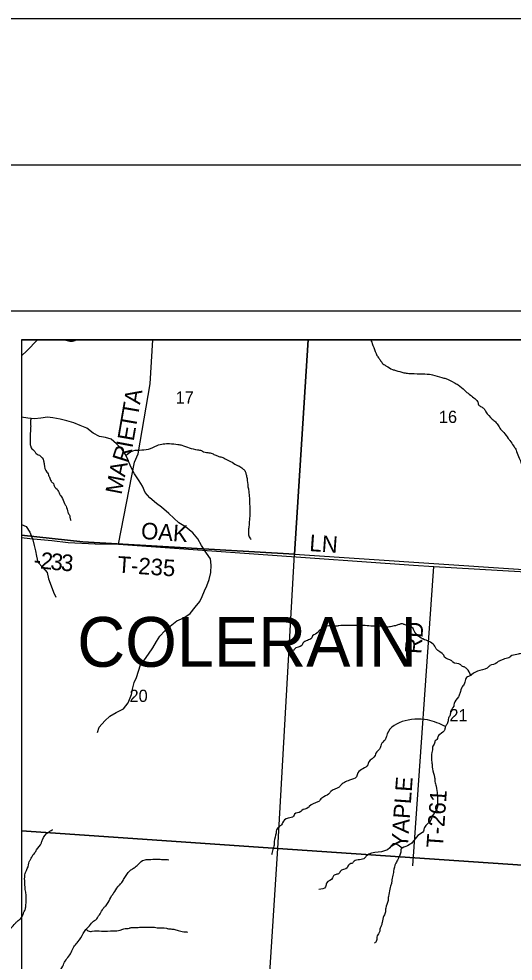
# Model space of a CAD drawing. Extents: x -13.1 to 43.1, y 0 to 22.
# Drawn here: x 2.09 to 3.786, y 18.772 to 22 of the extents above; entities that cross this region are included whole.
import ezdxf

# ---------------------------------------------------------------- set-up
doc = ezdxf.new("R2010")
doc.units = 0
for name, color, linetype in [('Default', 7, 'Continuous'), ('GM_X_Corporation', 7, 'Continuous'), ('GM_X_County_Road', 7, 'Continuous'), ('GM_X_County_Road_Text', 7, 'Continuous'), ('GM_X_Minor_River', 7, 'Continuous'), ('GM_X_Section_Text', 7, 'Continuous'), ('GM_X_State_Route', 7, 'Continuous'), ('GM_X_Township_Road', 7, 'Continuous'), ('GM_X_Township_Road_Text', 7, 'Continuous'), ('GM_X_Township_Text', 7, 'Continuous'), ('SH_Border', 7, 'Continuous'), ('SH_Data', 7, 'Continuous')]:
    doc.layers.add(name, color=color, linetype=linetype)

msp = doc.modelspace()

# ---------------------------------------------------------------- linework, layer by layer
at = {"layer": 'Default'}
msp.add_line((2.3057, 20.9), (2.2471, 20.9), dxfattribs=at)
for centre, major_axis, start_param, end_param in [((2.269, 20.9361), (0.0501, 0), 4.26168, 4.996735), ((2.2979, 20.8669), (0.0412, 0), 1.495662, 1.94098), ((2.3016, 20.9211), (0.0267, 0), 4.691044, 4.868584)]:
    msp.add_ellipse(centre, major_axis=major_axis, ratio=0.8, start_param=start_param, end_param=end_param, dxfattribs=at)
at = {"layer": 'GM_X_Corporation'}
for points in [[(7.0807, 20.9), (2.1, 20.9), (2.1, 14.1), (6.6193, 14.1), (6.6994, 15.2069), (6.7531, 15.956), (6.8236, 16.9075), (6.9509, 19.0179), (7.0108, 19.8446), (7.0164, 19.8954), (7.0617, 20.6133)], [(3.083, 20.9), (2.1, 20.9), (2.1, 20.2313), (2.31, 20.2083), (3.0353, 20.1657)], [(7.0804, 20.9), (2.1, 20.9), (2.1, 14.1), (6.619, 14.1), (6.6992, 15.2074), (6.7528, 15.9566), (6.8234, 16.908), (6.8365, 17.1257), (6.9507, 19.0184), (6.9616, 19.1692), (7.0106, 19.8452), (7.0162, 19.896), (7.0615, 20.6138)], [(7.0804, 20.9), (2.1, 20.9), (2.1, 17.2152), (2.1437, 17.2135), (2.8442, 17.1637), (3.8328, 17.0966), (4.4304, 17.0575), (6.8234, 16.908), (6.8365, 17.1257), (6.9507, 19.0184), (6.9616, 19.1692), (7.0106, 19.8452), (7.0162, 19.896), (7.0615, 20.6138)], [(4.0793, 20.9), (3.083, 20.9), (3.0353, 20.1657), (4.0252, 20.1002)], [(2.1, 20.2313), (2.1, 19.2176), (2.978, 19.1575), (3.0353, 20.1657), (2.31, 20.2083)], [(3.0353, 20.1657), (4.0252, 20.1002), (3.9684, 19.0905), (2.978, 19.1575)], [(2.1, 19.2176), (2.1, 18.2234), (2.9147, 18.1656), (2.978, 19.1575)], [(2.978, 19.1575), (3.9684, 19.0905), (3.9134, 18.1046), (2.9147, 18.1656)]]:
    msp.add_lwpolyline(points, close=True, dxfattribs=at)
at = {"layer": 'GM_X_County_Road'}
msp.add_lwpolyline([(2.1, 20.223), (2.1285, 20.22), (2.2036, 20.2129), (2.26, 20.206), (2.3521, 20.2017), (2.4322, 20.2003), (2.4865, 20.4809), (2.4991, 20.5096), (2.5404, 20.7501), (2.5504, 20.9)], dxfattribs=at)
at = {"layer": 'GM_X_Minor_River'}
for points in [[(2.36, 19.5553), (2.3662, 19.5727), (2.3853, 19.5953), (2.4029, 19.6111), (2.4242, 19.6238), (2.4492, 19.6358), (2.4653, 19.6561), (2.4769, 19.6849), (2.4801, 19.703), (2.4863, 19.7258), (2.494, 19.7439), (2.501, 19.7651), (2.5072, 19.7863), (2.521, 19.8044), (2.5356, 19.8232), (2.5501, 19.8451), (2.5624, 19.867), (2.5739, 19.8851), (2.5915, 19.9032), (2.6098, 19.919), (2.6326, 19.937), (2.6562, 19.9482), (2.6775, 19.9632), (2.6951, 19.9843), (2.7111, 20.0039), (2.7189, 20.0213), (2.7273, 20.0402), (2.7351, 20.0576), (2.7436, 20.0795), (2.7491, 20.1037), (2.75, 20.128), (2.7472, 20.15), (2.7337, 20.1691), (2.7165, 20.1958), (2.7046, 20.2187), (2.6866, 20.2393), (2.6617, 20.26), (2.6391, 20.2731), (2.6053, 20.3052), (2.5798, 20.3274), (2.5624, 20.3397), (2.5391, 20.3589), (2.5241, 20.3772), (2.5145, 20.3993), (2.5033, 20.4168), (2.4868, 20.4412), (2.4749, 20.4656), (2.4645, 20.49), (2.4563, 20.5075), (2.4451, 20.525), (2.4256, 20.5442), (2.4075, 20.5595), (2.3879, 20.5657), (2.3675, 20.5689), (2.3456, 20.5805), (2.323, 20.5981), (2.3004, 20.6067), (2.2785, 20.6159), (2.2551, 20.623), (2.2317, 20.6285), (2.2075, 20.6332), (2.1886, 20.6349), (2.1658, 20.632), (2.1446, 20.6299), (2.1212, 20.6317), (2.1, 20.6349)], [(2.1, 20.2674), (2.1151, 20.2607), (2.1286, 20.2408), (2.1382, 20.215), (2.1434, 20.1952), (2.147, 20.177), (2.1514, 20.1587), (2.155, 20.139), (2.1723, 20.1206), (2.1873, 20.103), (2.1924, 20.081), (2.2013, 20.0574), (2.2095, 20.0353), (2.2169, 20.0186)]]:
    msp.add_lwpolyline(points, dxfattribs=at)
for points in [[(3.2976, 20.9), (3.3036, 20.8839), (3.3081, 20.874), (3.3184, 20.8467), (3.3255, 20.8367), (3.3329, 20.8258), (3.3369, 20.8207), (3.3416, 20.8161), (3.3464, 20.813), (3.3514, 20.8103), (3.3713, 20.799), (3.383, 20.7955), (3.4109, 20.7875), (3.4275, 20.7854), (3.4656, 20.7841), (3.4988, 20.7821), (3.509, 20.7804), (3.5407, 20.7713), (3.555, 20.7673), (3.5839, 20.7533), (3.5967, 20.7463), (3.6196, 20.7267), (3.6504, 20.7021), (3.6635, 20.689), (3.6649, 20.6864), (3.6655, 20.6834), (3.666, 20.6803), (3.6672, 20.6776), (3.6715, 20.6738), (3.6767, 20.6707), (3.6818, 20.6677), (3.686, 20.6637), (3.692, 20.6538), (3.7141, 20.6289), (3.725, 20.6189), (3.7303, 20.6124), (3.735, 20.6053), (3.7396, 20.5981), (3.7448, 20.5914), (3.7534, 20.583), (3.7684, 20.5627), (3.7747, 20.5551), (3.7863, 20.5368), (3.7945, 20.5257), (3.7971, 20.5177), (3.806, 20.4953), (3.8105, 20.4858), (3.8201, 20.4546), (3.8245, 20.4413), (3.827, 20.4327), (3.8291, 20.4241), (3.8313, 20.4154), (3.8337, 20.4068), (3.8386, 20.3942), (3.8482, 20.3635), (3.8522, 20.3521), (3.8585, 20.3244), (3.8633, 20.3092), (3.8647, 20.2997), (3.8694, 20.2766), (3.872, 20.2694), (3.8761, 20.2515), (3.8798, 20.2432), (3.8809, 20.2375), (3.8857, 20.2238), (3.8891, 20.2185), (3.8984, 20.1994), (3.9007, 20.1962), (3.9033, 20.1932), (3.9061, 20.1903), (3.9085, 20.1872), (3.9122, 20.1796), (3.9298, 20.1593), (3.9354, 20.1556), (3.9418, 20.153), (3.9482, 20.1506), (3.9539, 20.1472), (3.9572, 20.1422), (3.9659, 20.1383), (3.9817, 20.1302)], [(2.1314, 20.6309), (2.1307, 20.6178), (2.131, 20.6053), (2.1306, 20.5947), (2.1292, 20.5637), (2.1291, 20.552), (2.1298, 20.5403), (2.1313, 20.5353), (2.1328, 20.5308), (2.1451, 20.5181), (2.1474, 20.5132), (2.1609, 20.5046), (2.1755, 20.4852), (2.1773, 20.4738), (2.1865, 20.4472), (2.1914, 20.4407), (2.1936, 20.4331), (2.1951, 20.4301), (2.2007, 20.4164), (2.2089, 20.4075), (2.2115, 20.3999), (2.2246, 20.3846), (2.2324, 20.3686), (2.2369, 20.3625), (2.2473, 20.3393), (2.2522, 20.3309), (2.2588, 20.3097), (2.2637, 20.2994), (2.2655, 20.2941), (2.2659, 20.2895), (2.2673, 20.2853), (2.2684, 20.2808)], [(2.4577, 20.5045), (2.4894, 20.5219), (2.4925, 20.5219), (2.5038, 20.5228), (2.5348, 20.5258), (2.5643, 20.5386), (2.5859, 20.544), (2.607, 20.5448), (2.6357, 20.5421), (2.6489, 20.5397), (2.6749, 20.5302), (2.7031, 20.5238), (2.7163, 20.5206), (2.7197, 20.5186), (2.7386, 20.5142), (2.7532, 20.5106), (2.766, 20.5048), (2.7766, 20.5008), (2.7894, 20.4972), (2.8074, 20.4875), (2.8165, 20.4836), (2.836, 20.472), (2.8451, 20.4681), (2.8582, 20.4588), (2.865, 20.4527), (2.8683, 20.4443), (2.8698, 20.4386), (2.8716, 20.4325), (2.8752, 20.4041), (2.8774, 20.3897), (2.8816, 20.3443), (2.8816, 20.2895), (2.8803, 20.2744), (2.8787, 20.2562), (2.8775, 20.2483), (2.8782, 20.2351), (2.8789, 20.229), (2.8826, 20.2218), (2.8864, 20.2157)], [(3.6401, 19.7509), (3.627, 19.773), (3.6172, 19.7795), (3.6082, 19.7835), (3.6056, 19.7865), (3.5785, 19.796), (3.5747, 19.8006), (3.5503, 19.8134), (3.5473, 19.8199), (3.521, 19.8414), (3.5169, 19.8502), (3.4816, 19.873), (3.4459, 19.9037), (3.4422, 19.9113), (3.4125, 19.9246), (3.4091, 19.9262), (3.3982, 19.9263), (3.3936, 19.9245), (3.3815, 19.9209), (3.3653, 19.9174), (3.3483, 19.9165), (3.3449, 19.9173), (3.3041, 19.9194), (3.2973, 19.9198), (3.2464, 19.9217), (3.2396, 19.9214), (3.1882, 19.9206), (3.1818, 19.9196), (3.1391, 19.9149), (3.1353, 19.9115), (3.1186, 19.9031), (3.1167, 19.8989), (3.0978, 19.8856), (3.0947, 19.8796), (3.0647, 19.8611), (3.0605, 19.8532), (3.0355, 19.8404), (3.0336, 19.8374), (3.0268, 19.8337), (3.0249, 19.8292), (3.0217, 19.8126)], [(4.6995, 19.316), (4.6907, 19.3151), (4.6877, 19.3166), (4.6824, 19.3197), (4.6696, 19.3245), (4.6501, 19.3368), (4.6459, 19.3414), (4.6026, 19.3519), (4.5962, 19.3561), (4.5503, 19.3704), (4.5458, 19.378), (4.5247, 19.3885), (4.5176, 19.3988), (4.4895, 19.4272), (4.4851, 19.4443), (4.4608, 19.4749), (4.4488, 19.4898), (4.4139, 19.5209), (4.4094, 19.5316), (4.3756, 19.5525), (4.3711, 19.5594), (4.3418, 19.5757), (4.3388, 19.5825), (4.3253, 19.5891), (4.3144, 19.5965), (4.308, 19.5996), (4.2929, 19.6047), (4.2794, 19.6117), (4.2771, 19.6144), (4.2564, 19.6256), (4.2531, 19.6306), (4.2241, 19.6446), (4.2204, 19.6504), (4.1899, 19.6655), (4.1862, 19.6713), (4.1575, 19.6841), (4.1538, 19.6895), (4.1256, 19.702), (4.1218, 19.707), (4.0921, 19.7199), (4.0884, 19.7245), (4.0609, 19.7362), (4.0575, 19.7408), (4.0338, 19.7506), (4.0308, 19.7548), (4.0079, 19.7642), (3.9917, 19.7708), (3.9887, 19.7746), (3.9789, 19.7786), (3.9529, 19.7865), (3.9499, 19.7896), (3.9311, 19.7978), (3.9288, 19.8005), (3.9134, 19.8075), (3.9115, 19.8105), (3.895, 19.8168), (3.8772, 19.8208), (3.8622, 19.8237), (3.8459, 19.8262), (3.8271, 19.8272), (3.8139, 19.8259), (3.7984, 19.8223), (3.7768, 19.8158), (3.7741, 19.8132), (3.7564, 19.8078), (3.7454, 19.8027), (3.7317, 19.7957), (3.7294, 19.7931), (3.706, 19.784), (3.7026, 19.7806), (3.6715, 19.7674), (3.6431, 19.7531), (3.637, 19.7486), (3.6287, 19.7453), (3.6207, 19.7322), (3.6191, 19.7236), (3.6111, 19.7119), (3.603, 19.689), (3.598, 19.677), (3.5831, 19.6541), (3.5816, 19.6454), (3.5709, 19.6259), (3.5701, 19.6176), (3.5655, 19.6075), (3.5616, 19.5913), (3.5593, 19.5845), (3.5532, 19.5755), (3.5512, 19.5653), (3.5443, 19.556), (3.5272, 19.5392), (3.5257, 19.5343), (3.5169, 19.5238), (3.5161, 19.5189), (3.5119, 19.5118), (3.5084, 19.496), (3.5065, 19.4866), (3.5059, 19.4586)], [(3.5532, 19.5755), (3.4914, 19.5979), (3.3509, 19.5417), (3.3494, 19.5353), (3.3422, 19.5259), (3.3315, 19.5098), (3.3299, 19.5027), (3.3147, 19.4844), (3.3124, 19.4765), (3.2907, 19.4541), (3.2869, 19.4443), (3.2534, 19.4168), (3.2484, 19.4036), (3.2246, 19.3915), (3.1927, 19.3723), (3.1885, 19.3678), (3.1601, 19.3531), (3.1571, 19.3486), (3.1358, 19.3345), (3.1241, 19.3248), (3.1218, 19.3211), (3.1161, 19.317), (3.0862, 19.3016), (3.0827, 19.2975), (3.0604, 19.2879), (3.0573, 19.2842), (3.0361, 19.2751), (3.0327, 19.2679), (3.0138, 19.2614), (2.9944, 19.2458), (2.9913, 19.2386), (2.9815, 19.2316), (2.9731, 19.2173), (2.9723, 19.2105), (2.9664, 19.1815), (2.9652, 19.1653), (2.9601, 19.1498), (2.9582, 19.1404), (2.9574, 19.1359)], [(3.5059, 19.4586), (3.5077, 19.4423), (3.5084, 19.4306), (3.5161, 19.401), (3.5171, 19.387), (3.5212, 19.3706), (3.5255, 19.3422), (3.5258, 19.3316), (3.526, 19.3067), (3.5252, 19.2961), (3.5194, 19.2852), (3.5065, 19.2646), (3.5037, 19.2552), (3.4813, 19.2298), (3.4778, 19.217), (3.4588, 19.2021), (3.4409, 19.1789), (3.4288, 19.17), (3.4045, 19.159), (3.4011, 19.1568), (3.4007, 19.1481), (3.3968, 19.1346), (3.3911, 19.1218), (3.383, 19.1068), (3.3753, 19.08), (3.3741, 19.071), (3.3694, 19.0503), (3.3686, 19.0404), (3.3648, 19.0288), (3.3632, 19.0186), (3.3577, 18.9933), (3.3565, 18.9793), (3.3484, 18.953), (3.3475, 18.9405), (3.3425, 18.9266), (3.336, 18.904), (3.3348, 18.8968), (3.3286, 18.8807), (3.3278, 18.8739), (3.3236, 18.8656), (3.3178, 18.8494), (3.317, 18.8419), (3.3106, 18.8329)], [(2.0074, 18.8227), (2.0213, 18.8323), (2.0233, 18.8372), (2.0313, 18.8492), (2.0362, 18.8555), (2.0472, 18.8644), (2.0568, 18.8787), (2.0644, 18.8854), (2.0777, 18.9011), (2.0857, 18.9081), (2.0967, 18.9182), (2.1055, 18.9328), (2.1063, 18.9377), (2.1108, 18.9456), (2.1139, 18.9573), (2.1143, 18.9618), (2.1155, 18.9705), (2.1153, 18.9901), (2.115, 18.9996), (2.1125, 19.0174), (2.1104, 19.0481), (2.1105, 19.0594), (2.1136, 19.0756), (2.124, 19.102), (2.1256, 19.1118), (2.1305, 19.12), (2.1401, 19.1365), (2.145, 19.1425), (2.1515, 19.153), (2.1676, 19.1766), (2.171, 19.1875), (2.192, 19.2137), (2.2014, 19.2192), (2.2071, 19.2229)], [(3.4045, 19.159), (3.3718, 19.1716), (3.3627, 19.1604), (3.282, 19.1317), (3.2733, 19.1227), (3.237, 19.1107), (3.2347, 19.107), (3.229, 19.1056), (3.2191, 19.097), (3.2165, 19.0917), (3.1922, 19.0785), (3.1891, 19.0725), (3.1782, 19.0685), (3.1683, 19.0618), (3.1664, 19.0565), (3.1459, 19.0391), (3.1424, 19.0266), (3.1189, 19.0167)], [(2.0714, 18.6008), (2.0885, 18.6082), (2.0923, 18.6203), (2.1086, 18.6303), (2.145, 18.6502), (2.1556, 18.6572), (2.1583, 18.6613), (2.1697, 18.6691), (2.1754, 18.6751), (2.1837, 18.6814), (2.1997, 18.6959), (2.2062, 18.7019), (2.2149, 18.7101), (2.2259, 18.7243), (2.2279, 18.7307), (2.2409, 18.7547), (2.2493, 18.772), (2.2619, 18.7884), (2.2818, 18.8244), (2.2928, 18.8375), (2.3115, 18.8664), (2.3203, 18.8795), (2.329, 18.8888), (2.3435, 18.9056), (2.3503, 18.9108), (2.3579, 18.9171), (2.364, 18.9272), (2.369, 18.934), (2.38, 18.9524), (2.3869, 18.9598), (2.3972, 18.9725), (2.4087, 18.9951), (2.4163, 19.0055), (2.4296, 19.0265), (2.4369, 19.0336), (2.446, 19.0441), (2.4536, 19.0587), (2.4586, 19.0651), (2.4685, 19.0789), (2.475, 19.0841), (2.4863, 19.0915), (2.4996, 19.103), (2.5141, 19.1161), (2.5235, 19.1193), (2.5303, 19.1196), (2.5341, 19.1196), (2.5428, 19.1202), (2.5707, 19.1209), (2.5881, 19.1199), (2.6043, 19.1193)], [(2.3215, 18.8808), (2.3357, 18.8732), (2.3418, 18.8742), (2.3738, 18.8746), (2.415, 18.8755), (2.438, 18.8778), (2.4502, 18.8822), (2.4702, 18.8849), (2.4728, 18.886), (2.4857, 18.887), (2.5042, 18.8878), (2.5072, 18.8882), (2.5242, 18.8883), (2.5521, 18.8875), (2.5555, 18.8875), (2.5653, 18.8862), (2.597, 18.8842), (2.6004, 18.8831), (2.6147, 18.8817), (2.6287, 18.8793), (2.6457, 18.8741), (2.666, 18.8715), (2.6687, 18.8711)]]:
    msp.add_spline(points, degree=3, dxfattribs=at)
at = {"layer": 'GM_X_State_Route'}
for p, q in [((2.1174, 20.863), (2.1544, 20.9)), ((2.1, 20.8456), (2.1174, 20.863))]:
    msp.add_line(p, q, dxfattribs=at)
at = {"layer": 'GM_X_Township_Road'}
msp.add_line((3.4413, 19.0983), (3.5132, 20.124), dxfattribs=at)
for points in [[(2.4322, 20.2003), (2.6566, 20.1843), (2.9283, 20.1652), (3.4438, 20.1288)], [(3.4438, 20.1288), (3.5132, 20.124), (4.0459, 20.0927), (4.5102, 20.0575)]]:
    msp.add_lwpolyline(points, dxfattribs=at)
at = {"layer": 'SH_Border'}
msp.add_lwpolyline([(1.5, 21.5), (33.5, 21.5), (33.5, 0.5), (1.5, 0.5)], close=True, dxfattribs=at)
at = {"layer": 'SH_Data'}
for p, q in [((2, 21), (9, 21)), ((2.1, 20.9), (2.1, 14.1)), ((2.1, 20.9), (8.9, 20.9))]:
    msp.add_line(p, q, dxfattribs=at)
msp.add_lwpolyline([(0, 0), (34, 0), (34, 22), (0, 22)], close=True, dxfattribs=at)

# ---------------------------------------------------------------- texts
at = {"layer": 'GM_X_County_Road_Text'}
for s, rotation, p in [('A', 80.1373, (2.5059, 20.6768)), ('T', 80.129, (2.4986, 20.6349)), ('T', 80.1357, (2.4913, 20.5931)), ('E', 80.0425, (2.484, 20.5511)), ('R', 72.5919, (2.4638, 20.4758)), ('I', 79.295, (2.4795, 20.5274)), ('A', 78.4993, (2.4542, 20.4283)), ('M', 79.0886, (2.4425, 20.3679)), ('2', 354.1822, (2.1621, 20.117)), ('3', 354.3132, (2.1971, 20.1134)), ('3', 355.7152, (2.2334, 20.1098)), ('-', 354.0688, (2.1388, 20.1194))]:
    msp.add_text(s, height=0.0568, rotation=rotation, dxfattribs=at).set_placement(p)
at = {"layer": 'GM_X_Section_Text'}
for s, p in [('17', (2.628, 20.6819)), ('16', (3.5309, 20.6155)), ('20', (2.47, 19.6597)), ('21', (3.5671, 19.5934))]:
    msp.add_text(s, height=0.04186, rotation=0, dxfattribs=at).set_placement(p)
at = {"layer": 'GM_X_Township_Road_Text'}
for s, rotation, p in [('OAK', 355.869, (2.5079, 20.2186)), ('LN', 355.876, (3.0854, 20.1769)), ('T-235', 356.0742, (2.427, 20.1029)), ('RD', 86.0533, (3.4705, 19.8228)), ('YAPLE', 85.9588, (3.4239, 19.157)), ('T-261', 86.0741, (3.5447, 19.1587))]:
    msp.add_text(s, height=0.05682, rotation=rotation, dxfattribs=at).set_placement(p)
at = {"layer": 'GM_X_Township_Text'}
msp.add_text('COLERAIN', height=0.17045, rotation=0, dxfattribs=at).set_placement((2.2904, 19.7802))

doc.saveas('drawing.dxf')
